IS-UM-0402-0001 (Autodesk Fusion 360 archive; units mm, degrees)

design "IS-UM-0402-0001" references "SFP SLOT", "Digitus_DN-651107_LAN-Switch 27mm", "ethernet 1 ports", "LED", "Ethernet Port", "Screw"
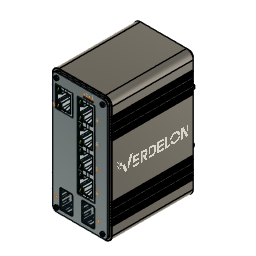
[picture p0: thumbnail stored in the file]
sketch "Sketch1" plane through (0, 0, 0) normal (0, 1, 0) x axis (1, 0, 0)
  line L1 (40, 0) -> (5, 0)
  line L2 (45, -90) -> (45, -5)
  line L3 (5, -95) -> (40, -95)
  line L4 (0, -5) -> (0, -90)
  arc A1 centre (5, -90) radius 5 clockwise from (5, -95) to (0, -90)
  arc A2 centre (40, -90) radius 5 clockwise from (45, -90) to (40, -95)
  arc A3 centre (40, -5) radius 5 clockwise from (40, 0) to (45, -5)
  arc A4 centre (5, -5) radius 5 clockwise from (0, -5) to (5, 0)
  point P1 (0, 0)
  point P2 (0, 0)
  point P4 (0, -95)
  point P3 (45, 0)
  horizontal L1
  vertical L2
  horizontal L3
  vertical L4
  coincident P1 P2
  coincident P4 L3
  coincident P4 L4
  tangent L3 A1
  tangent L4 A1
  tangent L2 A2
  tangent L3 A2
  equal A1 A2
  coincident P3 L1
  coincident P3 L2
  tangent L1 A3
  tangent L2 A3
  equal A1 A3
  coincident P2 L1
  coincident P2 L4
  tangent L1 A4
  tangent L4 A4
  equal A1 A4
  dimension "d1" distance P2 P3 = 45
  dimension "d2" distance P2 P4 = 95
  dimension "d3" radius A1 = 5
extrude "Extrude1" new body sketch "Sketch1" against normal blind 65
sketch "Sketch2" plane through (0, -65, 0) normal (0, -1, 0) x axis (1, 0, 0)
  line L1 (45, 90) -> (45, 5)
  line L2 (5, 95) -> (40, 95)
  line L3 (0, 5) -> (0, 90)
  line L4 (40, 0) -> (5, 0)
  line L5 (1.5, 5) -> (1.5, 90)
  line L6 (40, 1.5) -> (5, 1.5)
  line L7 (43.5, 90) -> (43.5, 5)
  line L8 (5, 93.5) -> (40, 93.5)
  line L9 (0, 5) -> (0, 90)
  line L10 (40, 0) -> (5, 0)
  line L11 (45, 90) -> (45, 5)
  line L12 (5, 95) -> (40, 95)
  arc A1 centre (40, 5) radius 5 clockwise from (45, 5) to (40, 0)
  arc A2 centre (40, 90) radius 5 clockwise from (40, 95) to (45, 90)
  arc A3 centre (5, 90) radius 5 clockwise from (0, 90) to (5, 95)
  arc A4 centre (5, 5) radius 5 clockwise from (5, 0) to (0, 5)
  arc A5 centre (5, 5) radius 3.5 clockwise from (5, 1.5) to (1.5, 5)
  arc A6 centre (40, 5) radius 3.5 clockwise from (43.5, 5) to (40, 1.5)
  arc A7 centre (40, 90) radius 3.5 clockwise from (40, 93.5) to (43.5, 90)
  arc A8 centre (5, 90) radius 3.5 clockwise from (1.5, 90) to (5, 93.5)
  arc A9 centre (5, 5) radius 5 clockwise from (5, 0) to (0, 5)
  arc A10 centre (40, 5) radius 5 clockwise from (45, 5) to (40, 0)
  arc A11 centre (40, 90) radius 5 clockwise from (40, 95) to (45, 90)
  arc A12 centre (5, 90) radius 5 clockwise from (0, 90) to (5, 95)
  dimension "d6" = -1.5
  dimension "d7" distance L3 = 0
extrude "Extrude2" cut sketch "Sketch2" against normal blind 1.5
sketch "Sketch3" plane through (0, 0, 0) normal (0, 1, 0) x axis (-1, 0, 0)
  line L1 (-5, 0) -> (-40, 0)
  line L2 (0, 90) -> (0, 5)
  line L3 (-40, 95) -> (-5, 95)
  line L4 (-45, 5) -> (-45, 90)
  line L5 (-43.5, 5) -> (-43.5, 90)
  line L6 (-5, 1.5) -> (-40, 1.5)
  line L7 (-1.5, 90) -> (-1.5, 5)
  line L8 (-40, 93.5) -> (-5, 93.5)
  line L9 (-45, 5) -> (-45, 90)
  line L10 (-5, 0) -> (-40, 0)
  line L11 (0, 90) -> (0, 5)
  line L12 (-40, 95) -> (-5, 95)
  arc A1 centre (-40, 5) radius 5 clockwise from (-40, 0) to (-45, 5)
  arc A2 centre (-5, 5) radius 5 clockwise from (0, 5) to (-5, 0)
  arc A3 centre (-5, 90) radius 5 clockwise from (-5, 95) to (0, 90)
  arc A4 centre (-40, 90) radius 5 clockwise from (-45, 90) to (-40, 95)
  arc A5 centre (-40, 5) radius 3.5 clockwise from (-40, 1.5) to (-43.5, 5)
  arc A6 centre (-5, 5) radius 3.5 clockwise from (-1.5, 5) to (-5, 1.5)
  arc A7 centre (-5, 90) radius 3.5 clockwise from (-5, 93.5) to (-1.5, 90)
  arc A8 centre (-40, 90) radius 3.5 clockwise from (-43.5, 90) to (-40, 93.5)
  arc A9 centre (-40, 5) radius 5 clockwise from (-40, 0) to (-45, 5)
  arc A10 centre (-5, 5) radius 5 clockwise from (0, 5) to (-5, 0)
  arc A11 centre (-5, 90) radius 5 clockwise from (-5, 95) to (0, 90)
  arc A12 centre (-40, 90) radius 5 clockwise from (-45, 90) to (-40, 95)
  dimension "d10" = -1.5
  dimension "d11" distance L4 = 0
extrude "Extrude3" cut sketch "Sketch3" against normal blind 1.5
sketch "Sketch6" plane through (0, -63.5, 0) normal (0, -1, 0) x axis (1, 0, 0)
  line L1 (40, 93.5) -> (5, 93.5)
  line L2 (43.5, 5) -> (43.5, 90)
  line L3 (5, 1.5) -> (40, 1.5)
  line L4 (1.5, 90) -> (1.5, 5)
  line L5 (0, 5) -> (0, 90)
  line L6 (40, 0) -> (5, 0)
  line L7 (45, 90) -> (45, 5)
  line L8 (5, 95) -> (40, 95)
  line L9 (-13, 47.5) -> (0, 47.5)
  line L10 (0.5, 67.5) -> (0, 67.5)
  line L11 (0.5, 68.5) -> (0.5, 67.5)
  line L12 (0, 68.5) -> (0.5, 68.5)
  line L13 (0, 67.5) -> (0, 68.5)
  line L14 (0, 69.25) -> (0, 70.25)
  line L15 (0.5, 70.25) -> (0.5, 69.25)
  line L16 (0, 70.25) -> (0.5, 70.25)
  line L17 (0.5, 69.25) -> (0, 69.25)
  line L18 (0, 71) -> (0, 72)
  line L19 (0.5, 72) -> (0.5, 71)
  line L20 (0, 72) -> (0.5, 72)
  line L21 (0.5, 71) -> (0, 71)
  line L22 (0, 75) -> (0, 76)
  line L23 (0, 77.75) -> (0.5, 77.75)
  line L24 (0, 76) -> (0.5, 76)
  line L25 (0.5, 76.75) -> (0, 76.75)
  line L26 (0.5, 73.25) -> (0, 73.25)
  line L27 (0.5, 77.75) -> (0.5, 76.75)
  line L28 (0.5, 75) -> (0, 75)
  line L29 (0, 74.25) -> (0.5, 74.25)
  line L30 (0.5, 74.25) -> (0.5, 73.25)
  line L31 (0.5, 76) -> (0.5, 75)
  line L32 (0, 73.25) -> (0, 74.25)
  line L33 (0, 76.75) -> (0, 77.75)
  line L34 (0, 80.75) -> (0, 81.75)
  line L35 (0, 83.5) -> (0.5, 83.5)
  line L36 (0, 81.75) -> (0.5, 81.75)
  line L37 (0.5, 82.5) -> (0, 82.5)
  line L38 (0.5, 79) -> (0, 79)
  line L39 (0.5, 83.5) -> (0.5, 82.5)
  line L40 (0.5, 80.75) -> (0, 80.75)
  line L41 (0, 80) -> (0.5, 80)
  line L42 (0.5, 80) -> (0.5, 79)
  line L43 (0.5, 81.75) -> (0.5, 80.75)
  line L44 (0, 79) -> (0, 80)
  line L45 (0, 82.5) -> (0, 83.5)
  line L46 (0, 20) -> (0, 19)
  line L47 (0.5, 20) -> (0, 20)
  line L48 (0.5, 25.75) -> (0, 25.75)
  line L49 (0, 12.5) -> (0, 11.5)
  line L50 (0, 21.75) -> (0, 20.75)
  line L51 (0, 13.25) -> (0.5, 13.25)
  line L52 (0, 20.75) -> (0.5, 20.75)
  line L53 (0.5, 17.25) -> (0.5, 18.25)
  line L54 (0, 16) -> (0, 15)
  line L55 (0.5, 12.5) -> (0, 12.5)
  line L56 (0, 11.5) -> (0.5, 11.5)
  line L57 (0.5, 24) -> (0, 24)
  line L58 (0, 24.75) -> (0.5, 24.75)
  line L59 (0, 26.5) -> (0.5, 26.5)
  line L60 (0, 25.75) -> (0, 24.75)
  line L61 (0.5, 24.75) -> (0.5, 25.75)
  line L62 (0.5, 14.25) -> (0, 14.25)
  line L63 (0.5, 21.75) -> (0, 21.75)
  line L64 (0.5, 13.25) -> (0.5, 14.25)
  line L65 (0, 18.25) -> (0, 17.25)
  line L66 (0, 24) -> (0, 23)
  line L67 (0.5, 27.5) -> (0, 27.5)
  line L68 (0.5, 26.5) -> (0.5, 27.5)
  line L69 (0.5, 23) -> (0.5, 24)
  line L70 (0.5, 19) -> (0.5, 20)
  line L71 (0.5, 16) -> (0, 16)
  line L72 (0.5, 20.75) -> (0.5, 21.75)
  line L73 (0, 23) -> (0.5, 23)
  line L74 (0, 27.5) -> (0, 26.5)
  line L75 (0, 14.25) -> (0, 13.25)
  line L76 (0.5, 18.25) -> (0, 18.25)
  line L77 (0, 19) -> (0.5, 19)
  line L78 (0, 15) -> (0.5, 15)
  line L79 (0.5, 15) -> (0.5, 16)
  line L80 (0.5, 11.5) -> (0.5, 12.5)
  line L81 (0, 17.25) -> (0.5, 17.25)
  line L82 (22.5, 102.41) -> (22.5, 95)
  line L83 (45, 74.25) -> (44.5, 74.25)
  line L84 (45, 80) -> (44.5, 80)
  line L85 (44.5, 80) -> (44.5, 79)
  line L86 (44.5, 83.5) -> (44.5, 82.5)
  line L87 (45, 80.75) -> (45, 81.75)
  line L88 (44.5, 82.5) -> (45, 82.5)
  line L89 (44.5, 80.75) -> (45, 80.75)
  line L90 (44.5, 72) -> (44.5, 71)
  line L91 (44.5, 76.75) -> (45, 76.75)
  line L92 (45, 79) -> (45, 80)
  line L93 (44.5, 68.5) -> (44.5, 67.5)
  line L94 (44.5, 76) -> (44.5, 75)
  line L95 (44.5, 75) -> (45, 75)
  line L96 (44.5, 81.75) -> (44.5, 80.75)
  line L97 (45, 82.5) -> (45, 83.5)
  line L98 (44.5, 79) -> (45, 79)
  line L99 (45, 71) -> (45, 72)
  line L100 (45, 72) -> (44.5, 72)
  line L101 (44.5, 74.25) -> (44.5, 73.25)
  line L102 (45, 77.75) -> (44.5, 77.75)
  line L103 (44.5, 71) -> (45, 71)
  line L104 (44.5, 73.25) -> (45, 73.25)
  line L105 (45, 76) -> (44.5, 76)
  line L106 (45, 83.5) -> (44.5, 83.5)
  line L107 (45, 68.5) -> (44.5, 68.5)
  line L108 (44.5, 77.75) -> (44.5, 76.75)
  line L109 (45, 69.25) -> (45, 70.25)
  line L110 (45, 70.25) -> (44.5, 70.25)
  line L111 (44.5, 69.25) -> (45, 69.25)
  line L112 (45, 75) -> (45, 76)
  line L113 (45, 76.75) -> (45, 77.75)
  line L114 (45, 67.5) -> (45, 68.5)
  line L115 (45, 73.25) -> (45, 74.25)
  line L116 (44.5, 67.5) -> (45, 67.5)
  line L117 (44.5, 70.25) -> (44.5, 69.25)
  line L118 (45, 81.75) -> (44.5, 81.75)
  line L119 (44.5, 14.25) -> (45, 14.25)
  line L120 (45, 21.75) -> (45, 20.75)
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  point P22 (0, 47.5)
  point P24 (0, 67.5)
  point P86 (0, 27.5)
  point P25 (0.5, 67.5)
  point P85 (0.5, 27.5)
  point P26 (0.5, 68.5)
  point P84 (0.5, 26.5)
  point P27 (0, 68.5)
  point P87 (0, 26.5)
  point P28 (0.5, 69.25)
  point P80 (0.5, 25.75)
  point P29 (0, 70.25)
  point P83 (0, 24.75)
  point P30 (0, 69.25)
  point P67 (0, 25.75)
  point P31 (0.5, 70.25)
  point P70 (0.5, 24.75)
  point P32 (0.5, 71)
  point P63 (0.5, 24)
  point P33 (0, 72)
  point P91 (0, 23)
  point P34 (0, 71)
  point P89 (0, 24)
  point P35 (0.5, 72)
  point P77 (0.5, 23)
  point P36 (0, 73.25)
  point P74 (0, 21.75)
  point P37 (0, 76)
  point P75 (0, 19)
  point P38 (0, 75)
  point P73 (0, 20)
  point P39 (0.5, 77.75)
  point P72 (0.5, 17.25)
  point P40 (0, 77.75)
  point P79 (0, 17.25)
  point P41 (0.5, 76)
  point P76 (0.5, 19)
  point P42 (0, 76.75)
  point P78 (0, 18.25)
  point P43 (0.5, 76.75)
  point P94 (0.5, 18.25)
  point P44 (0.5, 73.25)
  point P92 (0.5, 21.75)
  point P45 (0.5, 75)
  point P65 (0.5, 20)
  point P46 (0.5, 74.25)
  point P82 (0.5, 20.75)
  point P47 (0, 74.25)
  point P81 (0, 20.75)
  point P48 (0, 79)
  point P88 (0, 16)
  point P49 (0, 81.75)
  point P68 (0, 13.25)
  point P50 (0, 80.75)
  point P71 (0, 14.25)
  point P51 (0.5, 83.5)
  point P64 (0.5, 11.5)
  point P52 (0, 83.5)
  point P90 (0, 11.5)
  point P53 (0.5, 81.75)
  point P95 (0.5, 13.25)
  point P54 (0, 82.5)
  point P93 (0, 12.5)
  point P55 (0.5, 82.5)
  point P62 (0.5, 12.5)
  point P56 (0.5, 79)
  point P61 (0.5, 16)
  point P57 (0.5, 80.75)
  point P60 (0.5, 14.25)
  point P58 (0.5, 80)
  point P66 (0.5, 15)
  point P59 (0, 80)
  point P69 (0, 15)
  point P96 (22.5, 95)
  point P104 (45, 67.5)
  point P105 (44.5, 67.5)
  point P103 (44.5, 68.5)
  point P101 (45, 68.5)
  point P102 (44.5, 69.25)
  point P99 (45, 70.25)
  point P100 (45, 69.25)
  point P98 (44.5, 70.25)
  point P123 (44.5, 71)
  point P121 (45, 72)
  point P124 (45, 71)
  point P127 (44.5, 72)
  point P128 (45, 73.25)
  point P119 (45, 76)
  point P117 (45, 75)
  point P113 (44.5, 77.75)
  point P111 (45, 77.75)
  point P129 (44.5, 76)
  point P132 (45, 76.75)
  point P130 (44.5, 76.75)
  point P126 (44.5, 73.25)
  point P133 (44.5, 75)
  point P131 (44.5, 74.25)
  point P112 (45, 74.25)
  point P110 (45, 79)
  point P118 (45, 81.75)
  point P114 (45, 80.75)
  point P116 (44.5, 83.5)
  point P115 (45, 83.5)
  point P107 (44.5, 81.75)
  point P106 (45, 82.5)
  point P109 (44.5, 82.5)
  point P108 (44.5, 79)
  point P120 (44.5, 80.75)
  point P122 (44.5, 80)
  point P125 (45, 80)
  point P159 (44.5, 14.25)
  point P141 (44.5, 16)
  point P145 (44.5, 12.5)
  point P148 (44.5, 24)
  point P140 (44.5, 11.5)
  point P149 (44.5, 20)
  point P135 (44.5, 15)
  point P160 (45, 25.75)
  point P147 (45, 13.25)
  point P143 (45, 15)
  point P165 (44.5, 24.75)
  point P163 (45, 14.25)
  point P158 (44.5, 17.25)
  point P168 (45, 20)
  point P142 (45, 21.75)
  point P146 (45, 19)
  point P139 (44.5, 19)
  point P157 (44.5, 23)
  point P156 (45, 18.25)
  point P137 (45, 17.25)
  point P138 (44.5, 25.75)
  point P136 (45, 20.75)
  point P144 (44.5, 20.75)
  point P169 (45, 24.75)
  point P166 (44.5, 26.5)
  point P164 (44.5, 27.5)
  point P167 (45, 27.5)
  point P162 (45, 26.5)
  point P161 (45, 16)
  point P155 (45, 24)
  point P154 (45, 11.5)
  point P151 (45, 23)
  point P153 (44.5, 21.75)
  point P150 (45, 12.5)
  point P134 (44.5, 18.25)
  point P152 (44.5, 13.25)
  midpoint L5 P22
  perpendicular L5 L9
  horizontal L10
  vertical L11
  horizontal L12
  vertical L13
  coincident L5 P24
  symmetric L9 P24 P86
  symmetric L9 P25 P85
  symmetric L9 P26 P84
  symmetric L9 P27 P87
  symmetric L9 P28 P80
  symmetric L9 P29 P83
  symmetric L9 P30 P67
  symmetric L9 P31 P70
  symmetric L9 P32 P63
  symmetric L9 P33 P91
  symmetric L9 P34 P89
  symmetric L9 P35 P77
  symmetric L9 P36 P74
  symmetric L9 P37 P75
  symmetric L9 P38 P73
  symmetric L9 P39 P72
  symmetric L9 P40 P79
  symmetric L9 P41 P76
  symmetric L9 P42 P78
  symmetric L9 P43 P94
  symmetric L9 P44 P92
  symmetric L9 P45 P65
  symmetric L9 P46 P82
  symmetric L9 P47 P81
  symmetric L9 P48 P88
  symmetric L9 P49 P68
  symmetric L9 P50 P71
  symmetric L9 P51 P64
  symmetric L9 P52 P90
  symmetric L9 P53 P95
  symmetric L9 P54 P93
  symmetric L9 P55 P62
  symmetric L9 P56 P61
  symmetric L9 P57 P60
  symmetric L9 P58 P66
  symmetric L9 P59 P69
  midpoint L8 P96
  perpendicular L8 L82
  symmetric P24 L82 P104
  symmetric P25 L82 P105
  symmetric P26 L82 P103
  symmetric P27 L82 P101
  symmetric P28 L82 P102
  symmetric P29 L82 P99
  symmetric P30 L82 P100
  symmetric P31 L82 P98
  symmetric P32 L82 P123
  symmetric P33 L82 P121
  symmetric P34 L82 P124
  symmetric P35 L82 P127
  symmetric P36 L82 P128
  symmetric P37 L82 P119
  symmetric P38 L82 P117
  symmetric P39 L82 P113
  symmetric P40 L82 P111
  symmetric P41 L82 P129
  symmetric P42 L82 P132
  symmetric P43 L82 P130
  symmetric P44 L82 P126
  symmetric P45 L82 P133
  symmetric P46 L82 P131
  symmetric P47 L82 P112
  symmetric P48 L82 P110
  symmetric P49 L82 P118
  symmetric P50 L82 P114
  symmetric P51 L82 P116
  symmetric P52 L82 P115
  symmetric P53 L82 P107
  symmetric P54 L82 P106
  symmetric P55 L82 P109
  symmetric P56 L82 P108
  symmetric P57 L82 P120
  symmetric P58 L82 P122
  symmetric P59 L82 P125
  symmetric P60 L82 P159
  symmetric P61 L82 P141
  symmetric P62 L82 P145
  symmetric P63 L82 P148
  symmetric P64 L82 P140
  symmetric P65 L82 P149
  symmetric P66 L82 P135
  symmetric P67 L82 P160
  symmetric P68 L82 P147
  symmetric P69 L82 P143
  symmetric P70 L82 P165
  symmetric P71 L82 P163
  symmetric P72 L82 P158
  symmetric P73 L82 P168
  symmetric P74 L82 P142
  symmetric P75 L82 P146
  symmetric P76 L82 P139
  symmetric P77 L82 P157
  symmetric P78 L82 P156
  symmetric P79 L82 P137
  symmetric P80 L82 P138
  symmetric P81 L82 P136
  symmetric P82 L82 P144
  symmetric P83 L82 P169
  symmetric P84 L82 P166
  symmetric P85 L82 P164
  symmetric P86 L82 P167
  symmetric P87 L82 P162
  symmetric P88 L82 P161
  symmetric P89 L82 P155
  symmetric P90 L82 P154
  symmetric P91 L82 P151
  symmetric P92 L82 P153
  symmetric P93 L82 P150
  symmetric P94 L82 P134
  symmetric P95 L82 P152
  dimension "d24" distance P24 P27 = 1
  dimension "d25" distance P24 P25 = 0.5
  dimension "d38" distance L9 L10 = 20
  dimension "d41" R-Pattern1-uDistance = 0
  dimension "d42" R-Pattern1-vDistance = 3.5
  dimension "d45" R-Pattern2-uDistance = 0
  dimension "d46" R-Pattern2-vDistance = 11.5
extrude "Extrude4" cut sketch "Sketch6" against normal blind 78
fillet "Fillet1" radius 0.25
sketch "Sketch7" plane through (0, -65, 0) normal (0, -1, 0) x axis (1, 0, 0)
  line L1 (5, 93.25) -> (40, 93.25)
  line L2 (1.75, 5) -> (1.75, 90)
  line L3 (40, 1.75) -> (5, 1.75)
  line L4 (43.25, 90) -> (43.25, 5)
  line L5 (22.5, 47.5) -> (22.5, 93.25)
  line L6 (22.5, 47.5) -> (1.75, 47.5)
  line L7 (33.57, 85.5) -> (20.41, 85.5)
  line L8 (33.57, 21.7) -> (33.57, 85.5)
  line L9 (20.41, 21.7) -> (33.57, 21.7)
  line L10 (20.41, 85.5) -> (20.41, 21.7)
  line L11 (17, 85.5) -> (3.883, 85.5)
  line L12 (17, 69.55) -> (17, 85.5)
  line L13 (3.883, 69.55) -> (17, 69.55)
  line L14 (3.883, 85.5) -> (3.883, 69.55)
  line L15 (23.87, 19.2) -> (33.57, 19.2)
  line L16 (23.87, 4.7) -> (23.87, 19.2)
  line L17 (33.57, 4.7) -> (23.87, 4.7)
  line L18 (33.57, 19.2) -> (33.57, 4.7)
  line L19 (7.3, 19.2) -> (17, 19.2)
  line L20 (7.3, 4.7) -> (7.3, 19.2)
  line L21 (17, 4.7) -> (7.3, 4.7)
  line L22 (17, 19.2) -> (17, 4.7)
  arc A1 centre (5, 90) radius 3.25 clockwise from (1.75, 90) to (5, 93.25)
  arc A2 centre (5, 5) radius 3.25 clockwise from (5, 1.75) to (1.75, 5)
  arc A3 centre (40, 5) radius 3.25 clockwise from (43.25, 5) to (40, 1.75)
  arc A4 centre (40, 90) radius 3.25 clockwise from (40, 93.25) to (43.25, 90)
  circle C1 centre (31.77, 87.5) radius 0.75
  circle C2 centre (29.77, 87.5) radius 0.75
  circle C3 centre (27.77, 87.5) radius 0.75
  circle C4 centre (25.77, 87.5) radius 0.75
  circle C5 centre (5, 90) radius 0.85
  circle C6 centre (40, 90) radius 0.85
  circle C7 centre (40, 5) radius 0.85
  circle C8 centre (5, 5) radius 0.85
  point P14 (22.5, 93.25)
  point P15 (1.75, 47.5)
  point P18 (33.57, 85.5)
  point P19 (33.57, 21.7)
  point P17 (20.41, 85.5)
  point P21 (3.883, 85.5)
  point P24 (3.883, 69.55)
  point P22 (17, 85.5)
  point P25 (33.57, 19.2)
  point P28 (33.57, 4.7)
  point P26 (23.87, 19.2)
  point P29 (17, 19.2)
  point P30 (7.3, 19.2)
  point P31 (7.3, 4.7)
  point P33 (31.77, 87.5)
  midpoint L1 P14
  perpendicular L1 L5
  midpoint L2 P15
  perpendicular L5 L6
  horizontal L7
  vertical L8
  horizontal L9
  vertical L10
  horizontal L11
  vertical L12
  horizontal L13
  vertical L14
  collinear L7 L11
  horizontal L15
  vertical L16
  horizontal L17
  vertical L18
  horizontal L19
  vertical L20
  horizontal L21
  vertical L22
  collinear L15 L19
  collinear L8 L18
  collinear L12 L22
  concentric A1 C5
  dimension "d51" distance P18 P19 = 63.8
  dimension "d52" distance P17 P18 = 13.16
  dimension "d53" distance P21 P24 = 15.95
  dimension "d54" distance P21 P22 = 13.117 (= "13.16 mm - 0.043 mm")
  dimension "d55" distance L5 L12 = 5.5
  dimension "d56" distance L10 L12 = 3.41 (= "3.5 mm - 0.09 mm")
  dimension "d57" distance L6 L11 = 38
  dimension "d58" distance P25 P28 = 14.5
  dimension "d59" distance P25 P26 = 9.7
  dimension "d60" distance P29 P30 = 9.7
  dimension "d61" distance P30 P31 = 14.5
  dimension "d62" distance L9 L15 = 2.5
  dimension "d63" diameter C1 = 1.5
  dimension "d64" distance L7 P33 = 2
  dimension "d65" distance P18 P33 = 1.8
  dimension "d70" diameter C5 = 1.7
  dimension "d68" R-Pattern1-uDistance = -6
  dimension "d69" R-Pattern1-vDistance = 0
  dimension "d73" R-Pattern2-uDistance = 35
  dimension "d74" R-Pattern2-vDistance = 0
  dimension "d77" R-Pattern3-uDistance = 35
  dimension "d78" R-Pattern3-vDistance = 0
  dimension "d81" R-Pattern4-uDistance = 0
  dimension "d82" R-Pattern4-vDistance = -85
extrude "Extrude5" cut sketch "Sketch7" profile of L5 L6 L7 L8 L9 L10 L11 L12 L13 L14 L15 L16 L17 L18 L19 L20 L21 L22 C1 C2 C3 C4 C5 C6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 against normal blind 1
shell "Shell1" innerThickness 1
component_insert "Component Insert1"
component_insert "Component Insert3"
sketch "Sketch8" plane through (0, -65, 0) normal (0, -1, 0) x axis (1, 0, 0)
  line L1 (17, 69.55) -> (17, 85.5)
  line L2 (3.883, 69.55) -> (17, 69.55)
  line L3 (3.883, 85.5) -> (3.883, 69.55)
  line L4 (17, 85.5) -> (3.883, 85.5)
  line L5 (17, 19.2) -> (7.3, 19.2)
  line L6 (17, 4.7) -> (17, 19.2)
  line L7 (7.3, 4.7) -> (17, 4.7)
  line L8 (7.3, 19.2) -> (7.3, 4.7)
  line L9 (33.57, 19.2) -> (23.87, 19.2)
  line L10 (33.57, 4.7) -> (33.57, 19.2)
  line L11 (23.87, 4.7) -> (33.57, 4.7)
  line L12 (23.87, 19.2) -> (23.87, 4.7)
  line L13 (33.57, 21.7) -> (33.57, 85.5)
  line L14 (20.41, 21.7) -> (33.57, 21.7)
  line L15 (20.41, 85.5) -> (20.41, 21.7)
  line L16 (33.57, 85.5) -> (20.41, 85.5)
  line L17 (5, 93.25) -> (40, 93.25)
  line L18 (1.75, 5) -> (1.75, 90)
  line L19 (40, 1.75) -> (5, 1.75)
  line L20 (43.25, 90) -> (43.25, 5)
  circle C1 centre (29.77, 87.5) radius 0.75
  circle C2 centre (5, 90) radius 0.85
  circle C3 centre (31.77, 87.5) radius 0.75
  circle C4 centre (27.77, 87.5) radius 0.75
  circle C5 centre (40, 5) radius 0.85
  circle C6 centre (5, 5) radius 0.85
  circle C7 centre (25.77, 87.5) radius 0.75
  circle C8 centre (40, 90) radius 0.85
  arc A1 centre (5, 90) radius 3.25 clockwise from (1.75, 90) to (5, 93.25)
  arc A2 centre (5, 5) radius 3.25 clockwise from (5, 1.75) to (1.75, 5)
  arc A3 centre (40, 5) radius 3.25 clockwise from (43.25, 5) to (40, 1.75)
  arc A4 centre (40, 90) radius 3.25 clockwise from (40, 93.25) to (43.25, 90)
component_insert "Component Insert4"
rectangular_pattern "00000000-0000-0000-0000-000000000000" uSpaceDistance -16.58 vSpaceDistance 0
fillet "Fillet2" radius 1
component_insert "Component Insert5"
rectangular_pattern "00000000-0000-0000-0000-000000000000" uSpaceDistance 6 vSpaceDistance 0
component_insert "Component Insert8"
rectangular_pattern "00000000-0000-0000-0000-000000000000" uSpaceDistance -35 vSpaceDistance 0
rectangular_pattern "00000000-0000-0000-0000-000000000000" uSpaceDistance -85 vSpaceDistance 0
component_insert "Component Insert9"
decal "Decal1"
decal "Decal3"
sketch "Sketch9" plane through (0, -65, 0) normal (0, -1, 0) x axis (1, 0, 0)
  dimension "d102" = 1
  dimension "d103" = 1
  dimension "d104" = 1
  dimension "d105" = 1
  dimension "d106" = 1
  dimension "d107" = 1
  dimension "d108" = 1
  dimension "d109" = 1
  dimension "d110" = 1
  dimension "d111" = 1
  dimension "d112" = 1
sketch "Sketch10" plane through (0, 0, 0) normal (0, 0, 1) x axis (1, 0, 0)

design "Digitus_DN-651107_LAN-Switch 27mm"
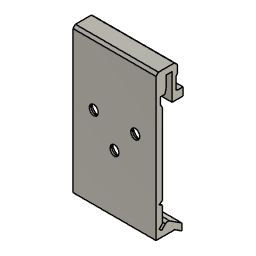
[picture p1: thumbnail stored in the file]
description: STEP AP214
part number: Digitus_DN-651107_LAN-Switch 27mm

design "Screw"
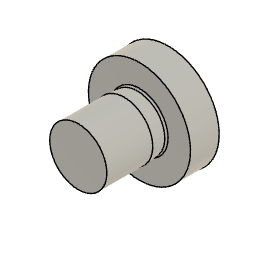
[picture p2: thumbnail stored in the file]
description: STEP AP214
part number: Screw

design "ethernet 1 ports"
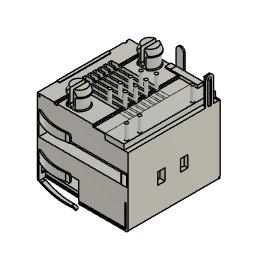
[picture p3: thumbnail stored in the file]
description: STEP AP214
part number: ethernet 1 ports

design "Ethernet Port"
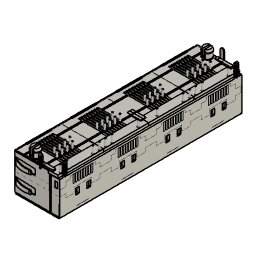
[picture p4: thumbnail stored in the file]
description: STEP AP214
part number: Ethernet Port

design "LED"
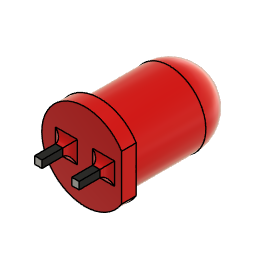
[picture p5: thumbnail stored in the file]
description: STEP AP214
part number: LED

design "SFP SLOT"
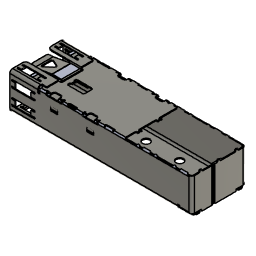
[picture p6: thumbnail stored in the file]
description: STEP AP214
part number: SFP SLOT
